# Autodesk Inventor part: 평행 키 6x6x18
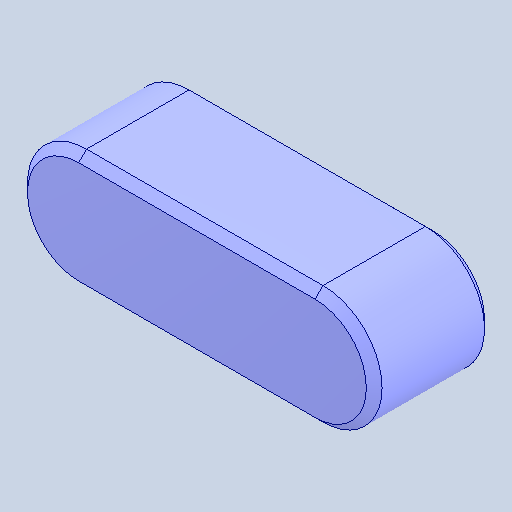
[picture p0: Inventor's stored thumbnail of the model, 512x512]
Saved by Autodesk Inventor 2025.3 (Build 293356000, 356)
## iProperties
Created: 2026-01
Part Number: 평행 키 6x6x18
Material: 강철, 연강
Description: 키 및 해당 키홈
Document SubType Name: Modeling
Designer: PC-13
Density: 7.85 g/cm^3
Appearance: 기본값
Author: jhkim
Sending System: Autodesk Inventor 2026
Preprocessor: ST-DEVELOPER v20.1
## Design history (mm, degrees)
feature "Solid1"
node "솔리드1"
